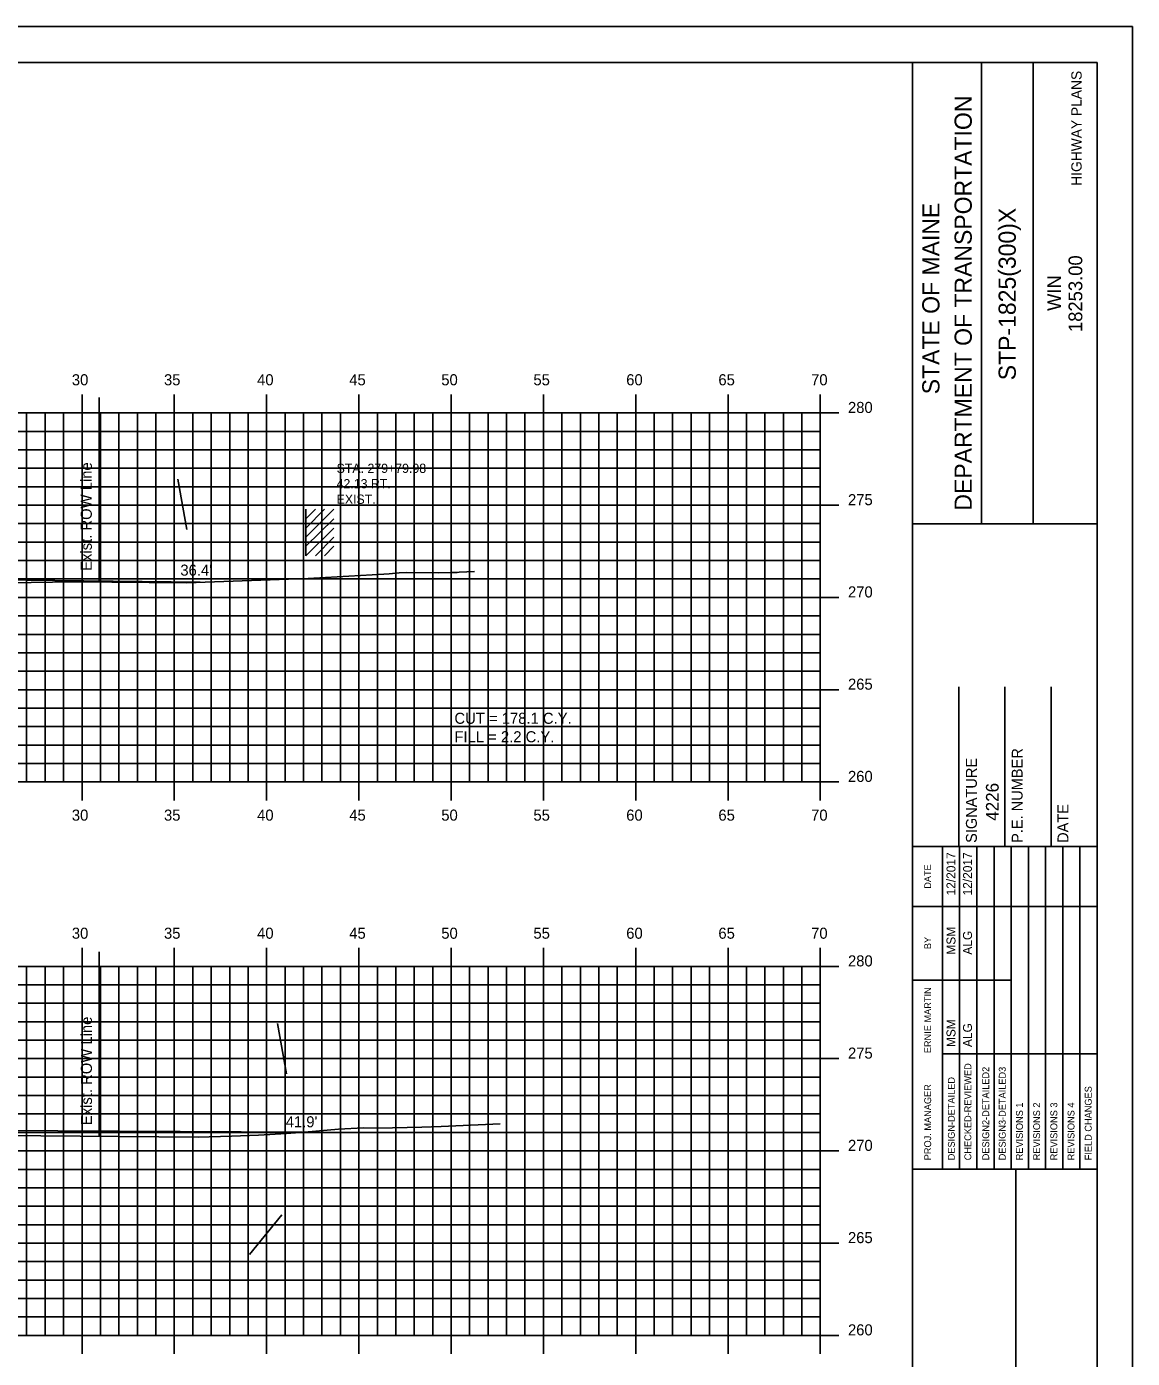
# Model space of a CAD drawing. Extents: x 854899 to 855069, y 366268 to 366378.
# Drawn here: x 855008.8 to 855068.7, y 366306 to 366378.2 of the extents above; entities that cross this region are included whole.
import ezdxf

# ---------------------------------------------------------------- set-up
doc = ezdxf.new("R2010")
doc.units = 0
for name, color, linetype in [('ANNOTATION', 7, 'Continuous'), ('BORDER', 7, 'Continuous'), ('D_Roadway_FinishedGrade', 7, 'Continuous'), ('D_Text_Monospaced', 7, 'Continuous'), ('D_Text_Standard', 7, 'Continuous'), ('E_ROW_Line', 7, 'Continuous'), ('H_V ANNOTATION', 7, 'Continuous'), ('HIGHWAY_TITLE', 7, 'Continuous'), ('MAJOR', 7, 'Continuous'), ('MINOR', 7, 'Continuous'), ('PLOT BOUNDARY', 7, 'Continuous'), ('S_Buildings_SillElevation', 7, 'Continuous'), ('S_Roadway_Centerline', 7, 'Continuous')]:
    doc.layers.add(name, color=color, linetype=linetype)

msp = doc.modelspace()

# ---------------------------------------------------------------- linework, layer by layer
at = {"layer": 'ANNOTATION'}
for p, q in [((855017.447, 366350.928), (855016.963, 366353.654)), ((855022.856, 366321.419), (855022.372, 366324.145)), ((855022.592, 366313.773), (855020.841, 366311.628))]:
    msp.add_line(p, q, dxfattribs=at)
at = {"layer": 'BORDER'}
for p, q in [((855066.774, 366376.236), (854906.774, 366376.236)), ((855056.774, 366271.236), (855056.774, 366376.239)), ((855060.503, 366351.234), (855060.503, 366376.234)), ((855063.298, 366351.234), (855063.298, 366376.234)), ((855066.774, 366271.236), (855066.774, 366376.236)), ((855056.775, 366351.231), (855066.774, 366351.231)), ((855059.274, 366333.739), (855059.274, 366342.387)), ((855061.774, 366333.739), (855061.774, 366342.387)), ((855064.274, 366333.739), (855064.274, 366342.387)), ((855056.774, 366333.739), (855066.774, 366333.739)), ((855056.774, 366316.239), (855066.774, 366316.239)), ((855062.365, 366281.239), (855062.365, 366316.239))]:
    msp.add_line(p, q, dxfattribs=at)
for points in [[(855058.389, 366330.489), (855058.389, 366333.739)], [(855059.322, 366316.242), (855059.322, 366333.739)], [(855060.253, 366333.739), (855060.253, 366316.242)], [(855061.185, 366316.242), (855061.185, 366333.739)], [(855062.117, 366316.242), (855062.117, 366333.739)], [(855063.048, 366316.242), (855063.048, 366333.739)], [(855063.98, 366316.242), (855063.98, 366333.739)], [(855064.912, 366316.242), (855064.912, 366333.739)], [(855065.844, 366316.242), (855065.844, 366333.739)], [(855058.39, 366316.242), (855058.39, 366333.033)], [(855056.774, 366330.489), (855066.774, 366330.489)], [(855056.774, 366326.489), (855058.39, 366326.489)], [(855058.389, 366326.489), (855062.116, 366326.489)], [(855058.389, 366322.489), (855066.774, 366322.489)]]:
    msp.add_lwpolyline(points, dxfattribs=at)
at = {"layer": 'D_Roadway_FinishedGrade'}
for p, q in [((855005.782, 366348.198), (855018.174, 366348.058)), ((855005.782, 366318.34), (855023.706, 366318.244))]:
    msp.add_line(p, q, dxfattribs=at)
at = {"layer": 'E_ROW_Line'}
for p, q in [((855012.704, 366348.076), (855012.704, 366358.076)), ((855012.711, 366318.028), (855012.711, 366328.028))]:
    msp.add_line(p, q, dxfattribs=at)
at = {"layer": 'MAJOR'}
for p, q in [((855011.774, 366358.238), (855011.774, 366357.236)), ((855016.774, 366358.238), (855016.774, 366357.236)), ((855021.774, 366358.238), (855021.774, 366357.236)), ((855026.774, 366358.238), (855026.774, 366357.236)), ((855031.774, 366358.238), (855031.774, 366357.236)), ((855036.774, 366358.238), (855036.774, 366357.236)), ((855041.774, 366358.238), (855041.774, 366357.236)), ((855046.774, 366358.238), (855046.774, 366357.236)), ((855051.774, 366358.238), (855051.774, 366357.236)), ((854911.774, 366357.236), (855051.774, 366357.236)), ((854911.774, 366357.236), (855051.774, 366357.236)), ((855011.774, 366337.236), (855011.774, 366357.236)), ((855016.774, 366337.236), (855016.774, 366357.236)), ((855021.774, 366337.236), (855021.774, 366357.236)), ((855026.774, 366337.236), (855026.774, 366357.236)), ((855031.774, 366337.236), (855031.774, 366357.236)), ((855036.774, 366337.236), (855036.774, 366357.236)), ((855041.774, 366337.236), (855041.774, 366357.236)), ((855046.774, 366337.236), (855046.774, 366357.236)), ((855052.776, 366357.236), (855050.772, 366357.236)), ((855051.774, 366337.236), (855051.774, 366357.236)), ((855051.774, 366337.236), (855051.774, 366357.236)), ((854911.774, 366352.236), (855051.774, 366352.236)), ((855052.776, 366352.236), (855050.772, 366352.236)), ((854911.774, 366347.236), (855051.774, 366347.236)), ((855052.776, 366347.236), (855050.772, 366347.236)), ((854911.774, 366342.236), (855051.774, 366342.236)), ((855052.776, 366342.236), (855050.772, 366342.236)), ((854911.774, 366337.236), (855051.774, 366337.236)), ((854911.774, 366337.236), (855051.774, 366337.236)), ((855011.774, 366336.234), (855011.774, 366337.236)), ((855016.774, 366336.234), (855016.774, 366337.236)), ((855021.774, 366336.234), (855021.774, 366337.236)), ((855026.774, 366336.234), (855026.774, 366337.236)), ((855031.774, 366336.234), (855031.774, 366337.236)), ((855036.774, 366336.234), (855036.774, 366337.236)), ((855041.774, 366336.234), (855041.774, 366337.236)), ((855046.774, 366336.234), (855046.774, 366337.236)), ((855052.776, 366337.236), (855050.772, 366337.236)), ((855051.774, 366336.234), (855051.774, 366337.236)), ((855011.774, 366328.238), (855011.774, 366327.236)), ((855016.774, 366328.238), (855016.774, 366327.236)), ((855021.774, 366328.238), (855021.774, 366327.236)), ((855026.774, 366328.238), (855026.774, 366327.236)), ((855031.774, 366328.238), (855031.774, 366327.236)), ((855036.774, 366328.238), (855036.774, 366327.236)), ((855041.774, 366328.238), (855041.774, 366327.236)), ((855046.774, 366328.238), (855046.774, 366327.236)), ((855051.774, 366328.238), (855051.774, 366327.236)), ((854911.774, 366327.236), (855051.774, 366327.236)), ((854911.774, 366327.236), (855051.774, 366327.236)), ((855011.774, 366307.236), (855011.774, 366327.236)), ((855016.774, 366307.236), (855016.774, 366327.236)), ((855021.774, 366307.236), (855021.774, 366327.236)), ((855026.774, 366307.236), (855026.774, 366327.236)), ((855031.774, 366307.236), (855031.774, 366327.236)), ((855036.774, 366307.236), (855036.774, 366327.236)), ((855041.774, 366307.236), (855041.774, 366327.236)), ((855046.774, 366307.236), (855046.774, 366327.236)), ((855052.776, 366327.236), (855050.772, 366327.236)), ((855051.774, 366307.236), (855051.774, 366327.236)), ((855051.774, 366307.236), (855051.774, 366327.236)), ((854911.774, 366322.236), (855051.774, 366322.236)), ((855052.776, 366322.236), (855050.772, 366322.236)), ((854911.774, 366317.236), (855051.774, 366317.236)), ((855052.776, 366317.236), (855050.772, 366317.236)), ((854911.774, 366312.236), (855051.774, 366312.236)), ((855052.776, 366312.236), (855050.772, 366312.236)), ((854911.774, 366307.236), (855051.774, 366307.236)), ((854911.774, 366307.236), (855051.774, 366307.236)), ((855011.774, 366306.234), (855011.774, 366307.236)), ((855016.774, 366306.234), (855016.774, 366307.236)), ((855021.774, 366306.234), (855021.774, 366307.236)), ((855026.774, 366306.234), (855026.774, 366307.236)), ((855031.774, 366306.234), (855031.774, 366307.236)), ((855036.774, 366306.234), (855036.774, 366307.236)), ((855041.774, 366306.234), (855041.774, 366307.236)), ((855046.774, 366306.234), (855046.774, 366307.236)), ((855052.776, 366307.236), (855050.772, 366307.236)), ((855051.774, 366306.234), (855051.774, 366307.236))]:
    msp.add_line(p, q, dxfattribs=at)
at = {"layer": 'MINOR'}
for p, q in [((855008.774, 366337.236), (855008.774, 366357.236)), ((855009.774, 366337.236), (855009.774, 366357.236)), ((855010.774, 366337.236), (855010.774, 366357.236)), ((855012.774, 366337.236), (855012.774, 366357.236)), ((855013.774, 366337.236), (855013.774, 366357.236)), ((855014.774, 366337.236), (855014.774, 366357.236)), ((855015.774, 366337.236), (855015.774, 366357.236)), ((855017.774, 366337.236), (855017.774, 366357.236)), ((855018.774, 366337.236), (855018.774, 366357.236)), ((855019.774, 366337.236), (855019.774, 366357.236)), ((855020.774, 366337.236), (855020.774, 366357.236)), ((855022.774, 366337.236), (855022.774, 366357.236)), ((855023.774, 366337.236), (855023.774, 366357.236)), ((855024.774, 366337.236), (855024.774, 366357.236)), ((855025.774, 366337.236), (855025.774, 366357.236)), ((855027.774, 366337.236), (855027.774, 366357.236)), ((855028.774, 366337.236), (855028.774, 366357.236)), ((855029.774, 366337.236), (855029.774, 366357.236)), ((855030.774, 366337.236), (855030.774, 366357.236)), ((855032.774, 366337.236), (855032.774, 366357.236)), ((855033.774, 366337.236), (855033.774, 366357.236)), ((855034.774, 366337.236), (855034.774, 366357.236)), ((855035.774, 366337.236), (855035.774, 366357.236)), ((855037.774, 366337.236), (855037.774, 366357.236)), ((855038.774, 366337.236), (855038.774, 366357.236)), ((855039.774, 366337.236), (855039.774, 366357.236)), ((855040.774, 366337.236), (855040.774, 366357.236)), ((855042.774, 366337.236), (855042.774, 366357.236)), ((855043.774, 366337.236), (855043.774, 366357.236)), ((855044.774, 366337.236), (855044.774, 366357.236)), ((855045.774, 366337.236), (855045.774, 366357.236)), ((855047.774, 366337.236), (855047.774, 366357.236)), ((855048.774, 366337.236), (855048.774, 366357.236)), ((855049.774, 366337.236), (855049.774, 366357.236)), ((855050.774, 366337.236), (855050.774, 366357.236)), ((854911.774, 366356.236), (855051.774, 366356.236)), ((855051.774, 366356.236), (855050.772, 366356.236)), ((854911.774, 366355.236), (855051.774, 366355.236)), ((855051.774, 366355.236), (855050.772, 366355.236)), ((854911.774, 366354.236), (855051.774, 366354.236)), ((855051.774, 366354.236), (855050.772, 366354.236)), ((854911.774, 366353.236), (855051.774, 366353.236)), ((855051.774, 366353.236), (855050.772, 366353.236)), ((854911.774, 366351.236), (855051.774, 366351.236)), ((855051.774, 366351.236), (855050.772, 366351.236)), ((854911.774, 366350.236), (855051.774, 366350.236)), ((855051.774, 366350.236), (855050.772, 366350.236)), ((854911.774, 366349.236), (855051.774, 366349.236)), ((855051.774, 366349.236), (855050.772, 366349.236)), ((854911.774, 366348.236), (855051.774, 366348.236)), ((855051.774, 366348.236), (855050.772, 366348.236)), ((854911.774, 366346.236), (855051.774, 366346.236)), ((855051.774, 366346.236), (855050.772, 366346.236)), ((854911.774, 366345.236), (855051.774, 366345.236)), ((855051.774, 366345.236), (855050.772, 366345.236)), ((854911.774, 366344.236), (855051.774, 366344.236)), ((855051.774, 366344.236), (855050.772, 366344.236)), ((854911.774, 366343.236), (855051.774, 366343.236)), ((855051.774, 366343.236), (855050.772, 366343.236)), ((854911.774, 366341.236), (855051.774, 366341.236)), ((855051.774, 366341.236), (855050.772, 366341.236)), ((854911.774, 366340.236), (855051.774, 366340.236)), ((855051.774, 366340.236), (855050.772, 366340.236)), ((854911.774, 366339.236), (855051.774, 366339.236)), ((855051.774, 366339.236), (855050.772, 366339.236)), ((854911.774, 366338.236), (855051.774, 366338.236)), ((855051.774, 366338.236), (855050.772, 366338.236)), ((855008.774, 366307.236), (855008.774, 366327.236)), ((855009.774, 366307.236), (855009.774, 366327.236)), ((855010.774, 366307.236), (855010.774, 366327.236)), ((855012.774, 366307.236), (855012.774, 366327.236)), ((855013.774, 366307.236), (855013.774, 366327.236)), ((855014.774, 366307.236), (855014.774, 366327.236)), ((855015.774, 366307.236), (855015.774, 366327.236)), ((855017.774, 366307.236), (855017.774, 366327.236)), ((855018.774, 366307.236), (855018.774, 366327.236)), ((855019.774, 366307.236), (855019.774, 366327.236)), ((855020.774, 366307.236), (855020.774, 366327.236)), ((855022.774, 366307.236), (855022.774, 366327.236)), ((855023.774, 366307.236), (855023.774, 366327.236)), ((855024.774, 366307.236), (855024.774, 366327.236)), ((855025.774, 366307.236), (855025.774, 366327.236)), ((855027.774, 366307.236), (855027.774, 366327.236)), ((855028.774, 366307.236), (855028.774, 366327.236)), ((855029.774, 366307.236), (855029.774, 366327.236)), ((855030.774, 366307.236), (855030.774, 366327.236)), ((855032.774, 366307.236), (855032.774, 366327.236)), ((855033.774, 366307.236), (855033.774, 366327.236)), ((855034.774, 366307.236), (855034.774, 366327.236)), ((855035.774, 366307.236), (855035.774, 366327.236)), ((855037.774, 366307.236), (855037.774, 366327.236)), ((855038.774, 366307.236), (855038.774, 366327.236)), ((855039.774, 366307.236), (855039.774, 366327.236)), ((855040.774, 366307.236), (855040.774, 366327.236)), ((855042.774, 366307.236), (855042.774, 366327.236)), ((855043.774, 366307.236), (855043.774, 366327.236)), ((855044.774, 366307.236), (855044.774, 366327.236)), ((855045.774, 366307.236), (855045.774, 366327.236)), ((855047.774, 366307.236), (855047.774, 366327.236)), ((855048.774, 366307.236), (855048.774, 366327.236)), ((855049.774, 366307.236), (855049.774, 366327.236)), ((855050.774, 366307.236), (855050.774, 366327.236)), ((854911.774, 366326.236), (855051.774, 366326.236)), ((855051.774, 366326.236), (855050.772, 366326.236)), ((854911.774, 366325.236), (855051.774, 366325.236)), ((855051.774, 366325.236), (855050.772, 366325.236)), ((854911.774, 366324.236), (855051.774, 366324.236)), ((855051.774, 366324.236), (855050.772, 366324.236)), ((854911.774, 366323.236), (855051.774, 366323.236)), ((855051.774, 366323.236), (855050.772, 366323.236)), ((854911.774, 366321.236), (855051.774, 366321.236)), ((855051.774, 366321.236), (855050.772, 366321.236)), ((854911.774, 366320.236), (855051.774, 366320.236)), ((855051.774, 366320.236), (855050.772, 366320.236)), ((854911.774, 366319.236), (855051.774, 366319.236)), ((855051.774, 366319.236), (855050.772, 366319.236)), ((854911.774, 366318.236), (855051.774, 366318.236)), ((855051.774, 366318.236), (855050.772, 366318.236)), ((854911.774, 366316.236), (855051.774, 366316.236)), ((855051.774, 366316.236), (855050.772, 366316.236)), ((854911.774, 366315.236), (855051.774, 366315.236)), ((855051.774, 366315.236), (855050.772, 366315.236)), ((854911.774, 366314.236), (855051.774, 366314.236)), ((855051.774, 366314.236), (855050.772, 366314.236)), ((854911.774, 366313.236), (855051.774, 366313.236)), ((855051.774, 366313.236), (855050.772, 366313.236)), ((854911.774, 366311.236), (855051.774, 366311.236)), ((855051.774, 366311.236), (855050.772, 366311.236)), ((854911.774, 366310.236), (855051.774, 366310.236)), ((855051.774, 366310.236), (855050.772, 366310.236)), ((854911.774, 366309.236), (855051.774, 366309.236)), ((855051.774, 366309.236), (855050.772, 366309.236)), ((854911.774, 366308.236), (855051.774, 366308.236)), ((855051.774, 366308.236), (855050.772, 366308.236))]:
    msp.add_line(p, q, dxfattribs=at)
at = {"layer": 'PLOT BOUNDARY'}
msp.add_lwpolyline([(854898.681, 366268.177), (855068.681, 366268.177), (855068.681, 366378.177), (854898.681, 366378.177)], close=True, dxfattribs=at)
at = {"layer": 'S_Buildings_SillElevation'}
for p, q in [((855023.9, 366349.488), (855023.9, 366352.014)), ((855023.9, 366350.505), (855025.409, 366352.014)), ((855023.9, 366350.997), (855024.917, 366352.014)), ((855023.9, 366351.489), (855024.425, 366352.014)), ((855023.9, 366350.013), (855025.409, 366351.489)), ((855023.9, 366349.488), (855025.409, 366350.997)), ((855024.425, 366349.488), (855025.409, 366350.505)), ((855024.917, 366349.488), (855025.409, 366350.013))]:
    msp.add_line(p, q, dxfattribs=at)
at = {"layer": 'S_Roadway_Centerline'}
for points in [[(855005.503, 366347.986), (855011.351, 366348.088), (855017.458, 366348.034), (855022.969, 366348.218), (855023.706, 366348.242), (855028.119, 366348.498), (855028.41, 366348.52), (855028.962, 366348.567), (855029.363, 366348.588), (855031.088, 366348.569), (855031.788, 366348.584), (855032.091, 366348.595), (855032.212, 366348.601), (855033.03, 366348.636)], [(855007.414, 366318.074), (855018.059, 366317.982), (855019.874, 366318.042), (855021.339, 366318.09), (855022.849, 366318.178), (855023.824, 366318.253), (855025.673, 366318.409), (855027.019, 366318.48), (855027.795, 366318.472), (855030.187, 366318.524), (855031.225, 366318.558), (855031.638, 366318.579), (855034.433, 366318.699)]]:
    msp.add_lwpolyline(points, dxfattribs=at)

# ---------------------------------------------------------------- texts
at = {"layer": 'ANNOTATION'}
for s, p in [('CUT = 178.1 C.Y.', (855031.95, 366340.386)), ('FILL = 2.2 C.Y.', (855031.95, 366339.384))]:
    msp.add_text(s, height=0.6, dxfattribs=at).set_placement(p)
msp.add_text('4226', height=0.69, rotation=90, dxfattribs=at).set_placement((855061.439, 366335.13))
at = {"layer": 'BORDER'}
for s, height, p in [('DEPARTMENT OF TRANSPORTATION', 0.93176, (855059.981, 366351.942)), ('STATE OF MAINE', 0.93176, (855058.23, 366358.248)), ('STP-1825(300)X', 0.93176, (855062.366, 366359.008)), ('18253.00', 0.7453, (855065.97, 366361.623)), ('WIN', 0.7453, (855064.811, 366362.766)), ('P.E. NUMBER', 0.59055, (855062.735, 366333.932)), ('SIGNATURE', 0.5906, (855060.255, 366333.932)), ('DATE', 0.5906, (855065.215, 366333.932)), ('12/2017', 0.4845, (855059.097, 366331.081)), ('12/2017', 0.4845, (855059.992, 366331.081)), ('DATE', 0.3714, (855057.779, 366331.445)), ('MSM', 0.4845, (855059.097, 366327.872)), ('BY', 0.3714, (855057.779, 366328.174)), ('ALG', 0.4845, (855059.992, 366327.872)), ('ERNIE MARTIN', 0.37275, (855057.779, 366322.531)), ('MSM', 0.4845, (855059.097, 366322.863)), ('ALG', 0.4845, (855059.992, 366322.863)), ('CHECKED-REVIEWED', 0.37275, (855059.955, 366316.727)), ('DESIGN2-DETAILED2', 0.37275, (855060.924, 366316.727)), ('DESIGN3-DETAILED3', 0.37275, (855061.819, 366316.727)), ('PROJ. MANAGER', 0.37275, (855057.779, 366316.727)), ('DESIGN-DETAILED', 0.37275, (855059.061, 366316.727)), ('FIELD CHANGES', 0.37275, (855066.477, 366316.727)), ('REVISIONS 1', 0.37275, (855062.75, 366316.727)), ('REVISIONS 2', 0.37275, (855063.682, 366316.727)), ('REVISIONS 3', 0.37275, (855064.614, 366316.727)), ('REVISIONS 4', 0.37275, (855065.545, 366316.727))]:
    msp.add_text(s, height=height, rotation=90, dxfattribs=at).set_placement(p)
at = {"layer": 'D_Text_Monospaced'}
for s, height, p in [('STA. 279+79.98', 0.49998, (855025.567, 366353.986)), ('42.13 RT.', 0.5, (855025.567, 366353.152)), ('EXIST. ', 0.5, (855025.567, 366352.312))]:
    msp.add_text(s, height=height, dxfattribs=at).set_placement(p)
at = {"layer": 'D_Text_Standard'}
for s, p in [("36.4'", (855017.101, 366348.417)), ("41.9'", (855022.81, 366318.514))]:
    msp.add_text(s, height=0.6, dxfattribs=at).set_placement(p)
at = {"layer": 'E_ROW_Line'}
for p in [(855012.304, 366348.676), (855012.311, 366318.628)]:
    msp.add_text('Exist. ROW Line', height=0.6, rotation=90, dxfattribs=at).set_placement(p)
at = {"layer": 'H_V ANNOTATION'}
for s, p in [('30', (855011.223, 366358.736)), ('35', (855016.215, 366358.736)), ('40', (855021.26, 366358.736)), ('45', (855026.252, 366358.736)), ('50', (855031.239, 366358.736)), ('55', (855036.231, 366358.736)), ('60', (855041.26, 366358.736)), ('65', (855046.252, 366358.736)), ('70', (855051.276, 366358.736)), ('280', (855053.274, 366357.236)), ('275', (855053.274, 366352.236)), ('270', (855053.274, 366347.236)), ('265', (855053.274, 366342.236)), ('260', (855053.274, 366337.236)), ('30', (855011.223, 366335.136)), ('35', (855016.215, 366335.136)), ('40', (855021.26, 366335.136)), ('45', (855026.252, 366335.136)), ('50', (855031.239, 366335.136)), ('55', (855036.231, 366335.136)), ('60', (855041.26, 366335.136)), ('65', (855046.252, 366335.136)), ('70', (855051.276, 366335.136)), ('30', (855011.223, 366328.736)), ('35', (855016.215, 366328.736)), ('40', (855021.26, 366328.736)), ('45', (855026.252, 366328.736)), ('50', (855031.239, 366328.736)), ('55', (855036.231, 366328.736)), ('60', (855041.26, 366328.736)), ('65', (855046.252, 366328.736)), ('70', (855051.276, 366328.736)), ('280', (855053.274, 366327.236)), ('275', (855053.274, 366322.236)), ('270', (855053.274, 366317.236)), ('265', (855053.274, 366312.236)), ('260', (855053.274, 366307.236))]:
    msp.add_text(s, height=0.6, dxfattribs=at).set_placement(p)
at = {"layer": 'HIGHWAY_TITLE'}
msp.add_text('HIGHWAY PLANS', height=0.55901, rotation=90, dxfattribs=at).set_placement((855065.933, 366369.552))

doc.saveas('drawing.dxf')
